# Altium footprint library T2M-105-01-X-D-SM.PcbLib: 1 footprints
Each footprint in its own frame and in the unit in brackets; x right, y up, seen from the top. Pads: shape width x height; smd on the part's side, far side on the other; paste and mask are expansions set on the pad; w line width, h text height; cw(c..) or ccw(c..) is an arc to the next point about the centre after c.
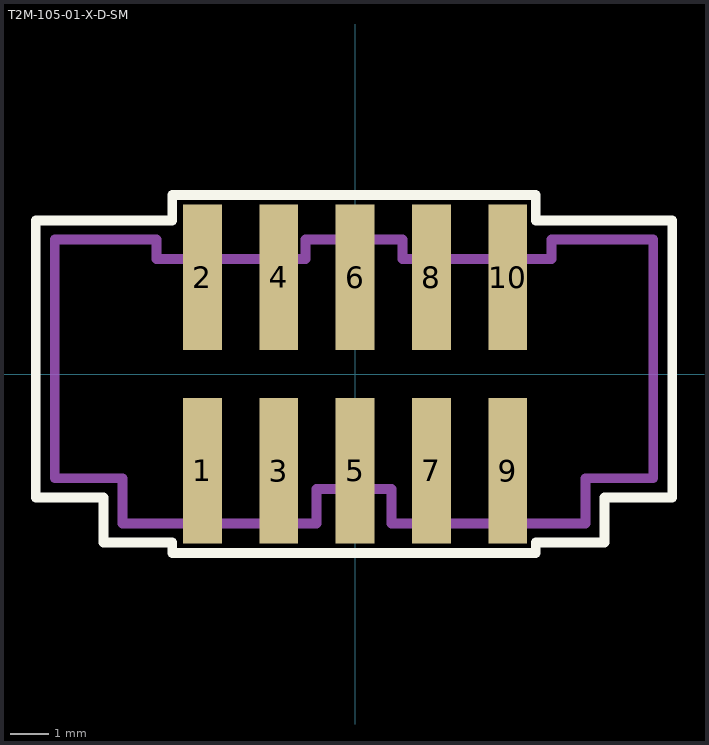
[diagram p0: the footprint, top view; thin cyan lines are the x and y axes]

## T2M-105-01-X-D-SM [mm]
pads (10):
  rect 1.02x3.8 smd mask+0.05: 1(-4,-2.535) 2(-4,2.535) 3(-2,-2.535) 4(-2,2.535) 5(0,-2.535) 6(0,2.535) 7(2,-2.535) 8(2,2.535) 9(4,-2.535) 10(4,2.535)
Top Overlay:
  lines w0.254: -8.365,-3.235 -6.592,-3.235 -6.592,-4.415 -4.79,-4.415 -4.79,-4.691 4.734,-4.691 4.734,-4.415 6.537,-4.415 6.537,-3.235 8.309,-3.235 8.309,4.023 4.734,4.023 4.734,4.691 -4.79,4.691 -4.79,4.023 -8.365,4.023 -8.365,-3.235
Mechanical 1:
  lines w0.254: -7.865,-2.735 -7.865,3.523 -5.203,3.523 -5.203,3.015 -1.298,3.015 -1.298,3.523 1.242,3.523 1.242,3.015 5.148,3.015 5.148,3.523 7.809,3.523 7.809,-2.735 6.037,-2.735 6.037,-3.915 0.956,-3.915 0.956,-3.015 -1.011,-3.015 -1.011,-3.915 -6.092,-3.915 -6.092,-2.735 -7.865,-2.735
  text "J1" at -0.497,-0.508 h0.76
